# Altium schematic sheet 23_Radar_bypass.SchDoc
size 289 x 400 mm
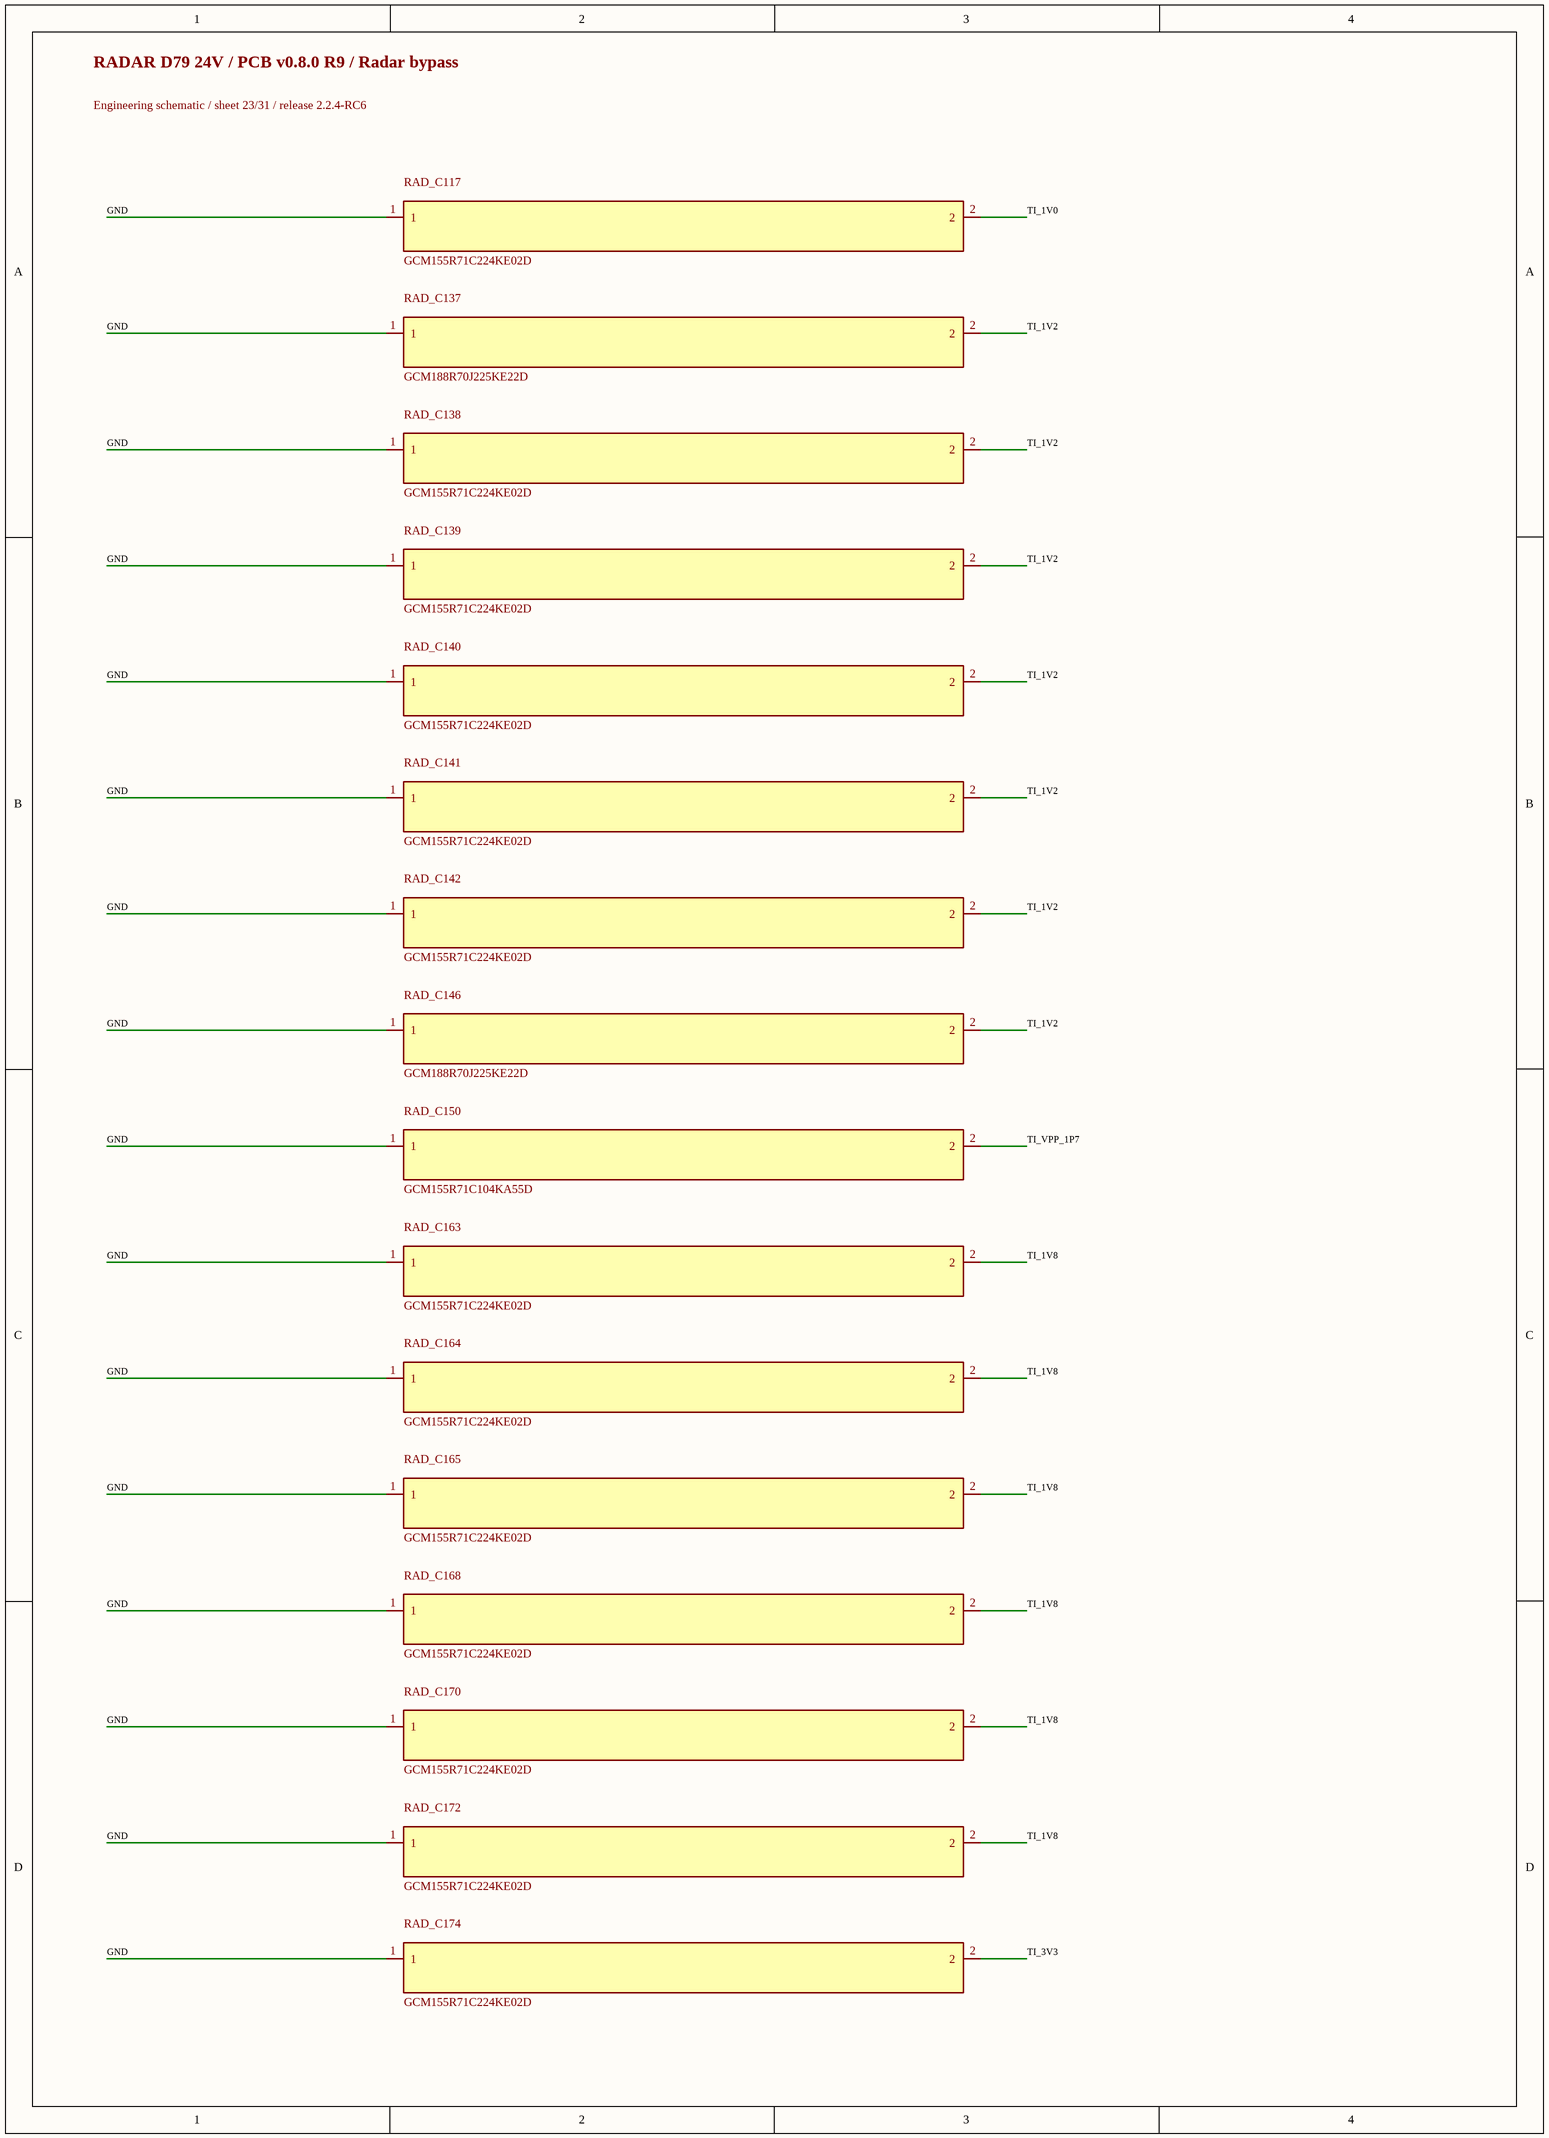
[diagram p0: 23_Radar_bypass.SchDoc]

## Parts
RAD_C117  GCM155R71C224KE02D  [0402L]
RAD_C137  GCM188R70J225KE22D  [0603L]
RAD_C138  GCM155R71C224KE02D  [0402L]
RAD_C139  GCM155R71C224KE02D  [0402L]
RAD_C140  GCM155R71C224KE02D  [0402L]
RAD_C141  GCM155R71C224KE02D  [0402L]
RAD_C142  GCM155R71C224KE02D  [0402L]
RAD_C146  GCM188R70J225KE22D  [0603L]
RAD_C150  GCM155R71C104KA55D  [0402L]
RAD_C163  GCM155R71C224KE02D  [0402L]
RAD_C164  GCM155R71C224KE02D  [0402L]
RAD_C165  GCM155R71C224KE02D  [0402L]
RAD_C168  GCM155R71C224KE02D  [0402L]
RAD_C170  GCM155R71C224KE02D  [0402L]
RAD_C172  GCM155R71C224KE02D  [0402L]
RAD_C174  GCM155R71C224KE02D  [0402L]

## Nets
GND: RAD_C117.1 RAD_C137.1 RAD_C138.1 RAD_C139.1 RAD_C140.1 RAD_C141.1 RAD_C142.1 RAD_C146.1 RAD_C150.1 RAD_C163.1 RAD_C164.1 RAD_C165.1 RAD_C168.1 RAD_C170.1 RAD_C172.1 RAD_C174.1
TI_1V0: RAD_C117.2
TI_1V2: RAD_C137.2 RAD_C138.2 RAD_C139.2 RAD_C140.2 RAD_C141.2 RAD_C142.2 RAD_C146.2
TI_1V8: RAD_C163.2 RAD_C164.2 RAD_C165.2 RAD_C168.2 RAD_C170.2 RAD_C172.2
TI_3V3: RAD_C174.2
TI_VPP_1P7: RAD_C150.2

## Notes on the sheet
- RADAR D79 24V / PCB v0.8.0 R9 / Radar bypass
- Engineering schematic / sheet 23/31 / release 2.2.4-RC6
